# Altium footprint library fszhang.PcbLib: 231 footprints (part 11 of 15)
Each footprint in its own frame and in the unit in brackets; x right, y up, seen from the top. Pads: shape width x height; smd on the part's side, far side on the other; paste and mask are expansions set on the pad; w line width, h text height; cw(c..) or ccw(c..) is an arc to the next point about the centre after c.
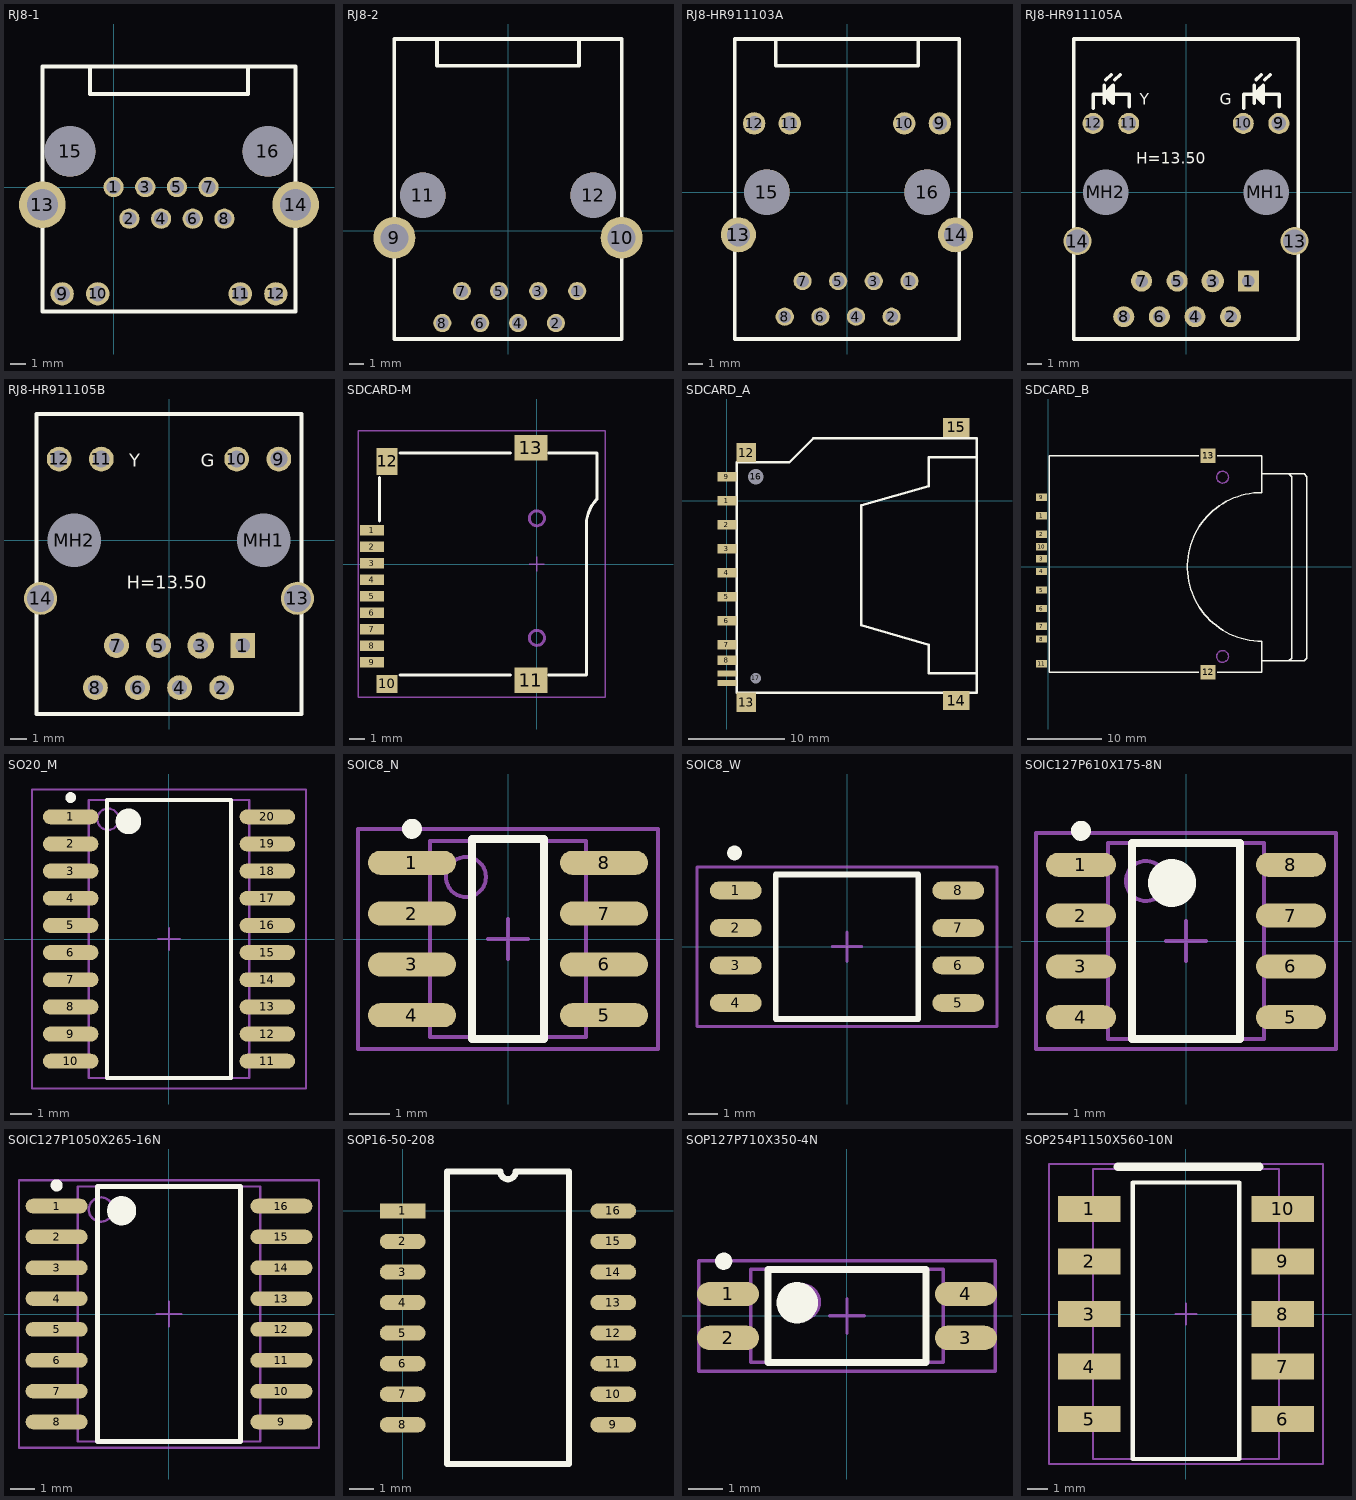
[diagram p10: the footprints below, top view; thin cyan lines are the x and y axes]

## RJ8-1 [mm] "网络"
pads (16):
  round 1.3 hole 0.9: 1(0,0) 2(1.016,-2.032) 3(2.032,0) 4(3.048,-2.032) 5(4.064,0) 6(5.08,-2.032) 7(6.096,0) 8(7.112,-2.032)
  round 1.5 hole 1: 9(-3.302,-6.858) 10(-1.016,-6.858) 11(8.128,-6.858)
  round 1.5 hole 0.9: 12(10.414,-6.858)
  round 3 hole 2: 13(-4.572,-1.143) 14(11.684,-1.143)
  round 3.251 hole 3.251: 15(-2.794,2.286) 16(9.906,2.286)
Top Overlay:
  lines w0.254: -1.524,7.747 -1.524,5.969 8.636,5.969 8.636,7.747 ; -4.572,-8.001 11.684,-8.001 11.684,-1.143 11.684,7.747 -4.572,7.747 -4.572,-1.143 -4.572,-8.001

## RJ8-2 [mm] "网络"
height 10
pads (12):
  round 1.3 hole 0.9: 1(4.953,-4.318) 2(3.429,-6.604) 3(2.159,-4.318) 4(0.72,-6.604) 5(-0.635,-4.318) 6(-1.99,-6.604) 7(-3.302,-4.318) 8(-4.699,-6.604)
  round 3 hole 2: 9(-8.128,-0.508) 10(8.128,-0.508)
  round 3.251 hole 3.251: 11(-6.096,2.54) 12(6.096,2.54)
Top Overlay:
  lines w0.254: -5.08,13.589 -5.08,11.811 5.08,11.811 5.08,13.589 ; -8.128,-7.747 8.128,-7.747 8.128,-0.889 8.128,13.716 -8.128,13.716 -8.128,-0.889 -8.128,-7.747

## RJ8-HR911103A [mm] "网络"
height 10
pads (16):
  round 1.3 hole 0.9: 1(4.45,-6.35) 2(3.18,-8.89) 3(1.91,-6.35) 4(0.64,-8.89) 5(-0.63,-6.35) 6(-1.9,-8.89) 7(-3.17,-6.35) 8(-4.44,-8.89)
  round 1.6 hole 1.02: 9(6.625,4.9) 10(4.085,4.9) 11(-4.085,4.9) 12(-6.625,4.9)
  round 2.5 hole 1.63: 13(-7.745,-3.05) 14(7.745,-3.05)
  round 3.251 hole 3.251: 15(-5.715,0) 16(5.715,0)
Top Overlay:
  lines w0.254: -5.08,10.795 -5.08,9.017 5.08,9.017 5.08,10.795 ; -8,-10.48 -8,10.92 8,10.92 8,-10.48 -8,-10.48

## RJ8-HR911105A [mm]
height 14.8
pads (16):
  rect 1.5x1.5 hole 0.9: 1(4.45,-6.35)
  round 1.5 hole 0.9: 2(3.18,-8.89) 4(0.64,-8.89) 5(-0.63,-6.35) 6(-1.9,-8.89) 7(-3.17,-6.35) 8(-4.44,-8.89)
  round 1.6 hole 0.9: 3(1.91,-6.35)
  round 1.5 hole 1.02: 9(6.625,4.9) 10(4.085,4.9) 11(-4.085,4.9) 12(-6.625,4.9)
  round 2 hole 1.63: 13(7.745,-3.5) 14(-7.745,-3.5)
  round 2.95 hole 3.25 unplated: MH1(5.715,0) MH2(-5.715,0)
Top Overlay:
  lines w0.25: -6.604,5.969 -6.604,6.985 -4.064,6.985 -4.064,6.096 ; -5.842,6.35 -5.842,7.62 ; -5.715,8.001 -5.334,8.382 ; -5.434,6.592 -5.434,7.393 ; -5.08,8.001 -4.699,8.382 ; 4.106,5.969 4.106,6.985 6.646,6.985 6.646,6.096 ; 4.868,6.35 4.868,7.62 ; 4.995,8.001 5.376,8.382 ; 5.276,6.592 5.276,7.393 ; 5.63,8.001 6.011,8.382 ; -8,-10.48 8,-10.48 8,10.92 -8,10.92 -8,-10.48 ; -5.842,6.985 -5.207,6.35 -5.207,7.62 -5.842,6.985 ; 4.868,6.985 5.503,6.35 5.503,7.62 4.868,6.985
  text "H=13.50" at -3.556,2.032 h0.8
  text "Y" at -3.302,6.223 h0.8
  text "G" at 2.413,6.223 h0.8

## RJ8-HR911105B [mm]
height 14.8
pads (16):
  rect 1.5x1.5 hole 0.9: 1(4.45,-6.35)
  round 1.5 hole 0.9: 2(3.18,-8.89) 4(0.64,-8.89) 5(-0.63,-6.35) 6(-1.9,-8.89) 7(-3.17,-6.35) 8(-4.44,-8.89)
  round 1.6 hole 0.9: 3(1.91,-6.35)
  round 1.5 hole 1.02: 9(6.625,4.9) 10(4.085,4.9) 11(-4.085,4.9) 12(-6.625,4.9)
  round 2 hole 1.63: 13(7.745,-3.5) 14(-7.745,-3.5)
  round 2.95 hole 3.25 unplated: MH1(5.715,0) MH2(-5.715,0)
Top Overlay:
  lines w0.25: -8,-10.48 -8,7.62 8,7.62 8,-10.48 -8,-10.48
  text "G" at 1.905,4.445 h0.8
  text "Y" at -2.413,4.445 h0.8
  text "H=13.50" at -2.54,-2.921 h0.8

## SDCARD-M [mm] "TF卡"
height 1.5
pads (13):
  rect 1.6x0.7 smd: 1(-11.008,2.25) 2(-11.008,1.15) 3(-11.008,0.05) 4(-11.008,-1.05) 5(-11.008,-2.15) 6(-11.008,-3.25) 7(-11.008,-4.35) 8(-11.008,-5.45) 9(-11.008,-6.55)
  rect 1.4x1.2 smd: 10(-10,-8.004)
  rect 2.2x1.7 smd: 11(-0.4,-7.75) 13(-0.4,7.75)
  rect 1.4x1.8 smd: 12(-10,6.85)
Top Overlay:
  lines w0.2: -10.5,2.88 -10.5,5.756 ; -9.144,-7.4 -1.778,-7.4 ; -9.144,7.4 -1.778,7.4 ; 0.762,-7.4 3.3,-7.4 3.3,1.016 ; 0.762,7.4 4,7.4 4,4.318 ccw(c5.69,2.628) 3.3,2.628 3.3,0.762
Mechanical 1:
  circle w0.2: c0,-4.93 r0.5
  circle w0.2: c0,3.05 r0.5
Mechanical 15:
  lines w0.1: -0.5,0 0.5,0 ; 0,-0.5 0,0.5 ; -11.938,-8.89 4.572,-8.89 4.572,8.89 -11.938,8.89 -11.938,-8.89

## SDCARD_A [mm] "SD卡不自弹"
pads (17):
  rect 2x1 smd: 1(0,0) 2(0,-2.5) 3(0,-5) 4(0,-7.5) 5(0,-10) 6(0,-12.5) 7(0,-15) 8(0,-16.625) 9(0,2.5)
  rect 2x0.6 smd: 10(0,-19) 11(0,-18)
  rect 2x2 smd: 12(2,5) 13(2,-21)
  rect 2.8x2 smd: 14(23.876,-20.828) 15(23.876,7.62)
  round 1.5 hole 1.6: 16(3,2.5)
  round 1 hole 1.1: 17(3,-18.5)
Top Overlay:
  lines w0.254: 26,-18 21,-18 21,-15 14,-13 14,-0.5 21,1.5 21,4.5 26,4.5 ; 1,-20 1,4 6.5,4 9,6.5 26,6.5 26,-20 1,-20

## SDCARD_B [mm] "SD卡自弹"
pads (13):
  rect 1.5x1 smd: 1(-0.889,6.88) 2(-0.889,4.38) 3(-0.889,1.08) 4(-0.889,-0.63) 5(-0.889,-3.13) 6(-0.889,-5.63) 7(-0.889,-8.05) 8(-0.889,-9.75) 9(-0.889,9.38) 10(-0.889,2.73) 11(-0.889,-13.1)
  rect 2x2 smd: 12(21.59,-14.224) 13(21.59,14.986)
Top Overlay:
  lines w0.2: 20.32,-14.224 0.127,-14.224 0.127,0 0.127,14.986 20.32,14.986 ; 22.86,-14.224 28.829,-14.224 28.829,-10.033 cw(c28.829,0) 28.829,10.033 28.829,14.986 22.86,14.986 ; 28.829,-12.7 32.893,-12.7 34.544,-12.7 34.925,-12.319 34.925,12.192 34.544,12.573 32.893,12.573 28.829,12.573 ; 32.512,-12.7 32.893,-12.319 32.893,12.192 32.512,12.573
Mechanical 1:
  circle w0.2: c23.55,12.1 r0.8
  circle w0.2: c23.55,-12.1 r0.8

## SO20_M [mm] "SOIC, 20-Leads, Body 12.8x7.5mm, Pitch 1.27mm, IPC Low Density"
height 2.65
pads (20):
  oval 2.6x0.7 smd: 1(-4.6,5.715) 2(-4.6,4.445) 3(-4.6,3.175) 4(-4.6,1.905) 5(-4.6,0.635) 6(-4.6,-0.635) 7(-4.6,-1.905) 8(-4.6,-3.175) 9(-4.6,-4.445) 10(-4.6,-5.715) 11(4.6,-5.715) 12(4.6,-4.445) 13(4.6,-3.175) 14(4.6,-1.905) 15(4.6,-0.635) 16(4.6,0.635) 17(4.6,1.905) 18(4.6,3.175) 19(4.6,4.445) 20(4.6,5.715)
Top Overlay:
  circle w0.6: c-1.9,5.5 r0.3
  circle w0.25: c-4.6,6.615 r0.125
  lines w0.2: -2.9,-6.5 2.9,-6.5 2.9,6.5 -2.9,6.5 -2.9,-6.5
Mechanical 13:
  circle w0.1: c-2.85,5.6 r0.5
  lines w0.1: -3.75,-6.5 3.75,-6.5 3.75,6.5 -3.75,6.5 -3.75,-6.5
Mechanical 15:
  lines w0.1: -0.5,0 0.5,0 ; 0,-0.5 0,0.5 ; -6.4,-7 6.4,-7 6.4,7 -6.4,7 -6.4,-7
3D body: height 2.65, standoff 0, extent -3.75,-6.5 3.75,6.5

## SOIC8_N [mm] "8-Pin Small Outline Integrated Circuit Package (SOIC8), IPC Medium Density"
height 1.75
pads (8):
  oval 2.2x0.6 smd: 1(-2.4,1.905) 2(-2.4,0.635) 3(-2.4,-0.635) 4(-2.4,-1.905) 5(2.4,-1.905) 6(2.4,-0.635) 7(2.4,0.635) 8(2.4,1.905)
Top Overlay:
  circle w0.25: c-2.4,2.755 r0.125
  lines w0.2: -0.9,-2.5 0.9,-2.5 0.9,2.5 -0.9,2.5 -0.9,-2.5
Mechanical 13:
  circle w0.1: c-1.05,1.55 r0.5
  lines w0.1: -1.95,-2.45 1.95,-2.45 1.95,2.45 -1.95,2.45 -1.95,-2.45
Mechanical 15:
  lines w0.1: -0.5,0 0.5,0 ; 0,-0.5 0,0.5 ; -3.75,-2.75 3.75,-2.75 3.75,2.75 -3.75,2.75 -3.75,-2.75
3D body: height 1.75, standoff 0, extent -1.95,-2.45 1.95,2.45

## SOIC8_W [mm] "SPI_FLASH"
height 1.75
pads (8):
  oval 1.75x0.6 smd: 1(-3.768,1.905) 2(-3.768,0.635) 3(-3.768,-0.635) 4(-3.768,-1.905) 5(3.768,-1.905) 6(3.768,-0.635) 7(3.768,0.635) 8(3.768,1.905)
Top Overlay:
  circle w0.25: c-3.808,3.175 r0.125
  lines w0.2: -2.413,-2.45 -2.413,2.45 2.413,2.45 2.413,-2.45 -2.413,-2.45
Mechanical 15:
  lines w0.1: -0.5,0 0.5,0 ; 0,-0.5 0,0.5 ; -5.08,-2.7 -5.08,2.7 5.08,2.7 5.08,-2.7 -5.08,-2.7

## SOIC127P610X175-8N [mm] "ACS712"
height 1.75
pads (8):
  oval 1.75x0.6 smd: 1(-2.625,1.905) 2(-2.625,0.635) 3(-2.625,-0.635) 4(-2.625,-1.905) 5(2.625,-1.905) 6(2.625,-0.635) 7(2.625,0.635) 8(2.625,1.905)
Top Overlay:
  circle w0.6: c-0.35,1.45 r0.3
  circle w0.25: c-2.625,2.755 r0.125
  lines w0.2: -1.35,-2.45 1.35,-2.45 1.35,2.45 -1.35,2.45 -1.35,-2.45
Mechanical 13:
  circle w0.1: c-1,1.5 r0.5
  lines w0.1: -1.95,-2.45 1.95,-2.45 1.95,2.45 -1.95,2.45 -1.95,-2.45
Mechanical 15:
  lines w0.1: -0.5,0 0.5,0 ; 0,-0.5 0,0.5 ; -3.75,-2.7 3.75,-2.7 3.75,2.7 -3.75,2.7 -3.75,-2.7
3D body: height 1, standoff 0.1, extent -1.95,-2.45 1.95,2.45

## SOIC127P1050X265-16N [mm] "SOIC SMB460"
height 2.65
pads (16):
  oval 2.55x0.6 smd: 1(-4.625,4.445) 2(-4.625,3.175) 3(-4.625,1.905) 4(-4.625,0.635) 5(-4.625,-0.635) 6(-4.625,-1.905) 7(-4.625,-3.175) 8(-4.625,-4.445) 9(4.625,-4.445) 10(4.625,-3.175) 11(4.625,-1.905) 12(4.625,-0.635) 13(4.625,0.635) 14(4.625,1.905) 15(4.625,3.175) 16(4.625,4.445)
Top Overlay:
  circle w0.6: c-1.95,4.25 r0.3
  circle w0.25: c-4.625,5.295 r0.125
  lines w0.2: -2.95,-5.25 2.95,-5.25 2.95,5.25 -2.95,5.25 -2.95,-5.25
Mechanical 13:
  circle w0.1: c-2.8,4.3 r0.5
  lines w0.1: -3.75,-5.25 3.75,-5.25 3.75,5.25 -3.75,5.25 -3.75,-5.25
Mechanical 15:
  lines w0.1: -0.5,0 0.5,0 ; 0,-0.5 0,0.5 ; -6.175,-5.5 6.175,-5.5 6.175,5.5 -6.175,5.5 -6.175,-5.5
3D body: height 2.65, standoff 0.1, extent -3.75,-5.25 3.75,5.25

## SOP16-50-208 [mil]
height 196.85
pads (16):
  rect 75x25 smd: 1(0,0)
  oval 75x25 smd: 2(0,-50) 3(0,-100) 4(0,-150) 5(0,-200) 6(0,-250) 7(0,-300) 8(0,-350) 9(345,-350) 10(345,-300) 11(345,-250) 12(345,-200) 13(345,-150) 14(345,-100) 15(345,-50) 16(345,0)
Top Overlay:
  lines w10: 72.5,-414.37 272.5,-414.37 272.5,64.37 185,64.37 cw(c172.5,64.37) 160,64.37 72.5,64.37 72.5,-414.37

## SOP127P710X350-4N [mm] "SOP, 4-Leads, Body 2.7x4.5mm (max), Pitch 1.27mm, IPC Medium Density"
height 3.5
pads (4):
  oval 1.8x0.7 smd: 1(-3.448,0.635) 2(-3.448,-0.635) 3(3.448,-0.635) 4(3.448,0.635)
Top Overlay:
  circle w0.6: c-1.443,0.381 r0.3
  circle w0.25: c-3.575,1.585 r0.125
  lines w0.2: -2.286,-1.35 2.286,-1.35 2.286,1.35 -2.286,1.35 -2.286,-1.35
Mechanical 13:
  circle w0.1: c-1.3,0.4 r0.5
  lines w0.1: -2.794,-1.35 2.794,-1.35 2.794,1.35 -2.794,1.35 -2.794,-1.35
Mechanical 15:
  lines w0.1: -0.5,0 0.5,0 ; 0,-0.5 0,0.5 ; -4.3,-1.6 4.3,-1.6 4.3,1.6 -4.3,1.6 -4.3,-1.6
3D body: height 3.5, standoff 0.25, extent -2.758,-1.35 2.794,1.35

## SOP254P1150X560-10N [mm] "双继电器"
height 5.6
pads (10):
  rect 3x1.25 smd: 1(-4.675,5.08) 2(-4.675,2.54) 3(-4.675,0) 4(-4.675,-2.54) 5(-4.675,-5.08) 6(4.675,-5.08) 7(4.675,-2.54) 8(4.675,0) 9(4.675,2.54) 10(4.675,5.08)
Top Overlay:
  lines w0.2: -2.575,-7 -2.575,6.35 2.575,6.35 2.575,-7 -2.575,-7
  lines w0.4: -3.302,7.112 3.556,7.112
Mechanical 13:
  lines w0.1: -4.5,-7 -4.5,7 4.5,7 4.5,-7 -4.5,-7
Mechanical 15:
  lines w0.1: -0.5,0 0.5,0 ; 0,-0.5 0,0.5 ; -6.625,-7.25 -6.625,7.25 6.625,7.25 6.625,-7.25 -6.625,-7.25
3D body: height 5.6, standoff 0.25, extent -4.5,-7 4.5,7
